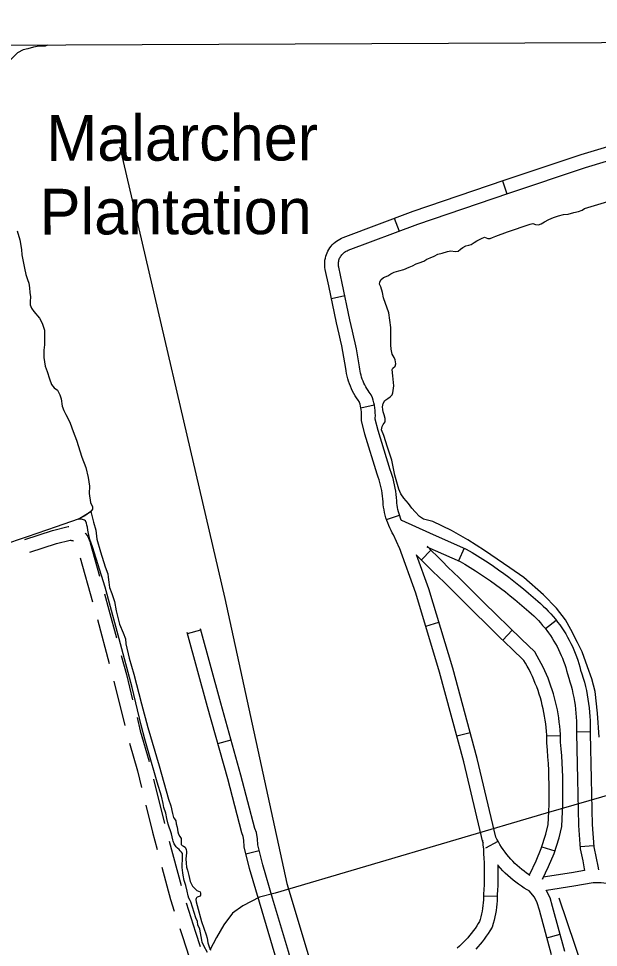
# Model space of a CAD drawing. Extents: x 3419139 to 3457078, y 540382 to 565875.
# Drawn here: x 3441511 to 3442779, y 562061 to 564093 of the extents above; entities that cross this region are included whole.
import ezdxf

# ---------------------------------------------------------------- set-up
doc = ezdxf.new("R2010")
doc.units = 0
for name, color, linetype in [('V-BLDG-IDEN', 7, 'Continuous'), ('V-GRID-FRAM', 7, 'Continuous'), ('V-ROAD-CNTR', 7, 'Continuous'), ('V-TOPO-SHOR', 7, 'Continuous')]:
    doc.layers.add(name, color=color, linetype=linetype)

msp = doc.modelspace()

# ---------------------------------------------------------------- linework, layer by layer
at = {"layer": 'V-GRID-FRAM'}
msp.add_lwpolyline([(3423200.9, 563955.1), (3454837.9, 564093.1), (3454925.2, 545910.2), (3423272.3, 545772.1), (3423200.9, 563955.1)], dxfattribs=at)
at = {"layer": 'V-ROAD-CNTR'}
for p, q in [((3442569.4, 563738.2), (3442579.1, 563709.8)), ((3442332.8, 563656.1), (3442343.4, 563628)), ((3442195.2, 563480.8), (3442224.5, 563487)), ((3442259.8, 563241.3), (3442289.1, 563247.7)), ((3442315.6, 562997.4), (3442344.2, 563006.5)), ((3442392.1, 562908.7), (3442413.1, 562930.1)), ((3442485.7, 562934.2), (3442473.6, 562906.8)), ((3441645.8, 562913.2), (3441672.8, 562816.9)), ((3441683.5, 562778.4), (3441709.4, 562681.8)), ((3442401.5, 562763.5), (3442430.2, 562772.2)), ((3442687.2, 562776.3), (3442663.5, 562757.8)), ((3441880.6, 562747.6), (3441909.5, 562755.6)), ((3442570, 562733.1), (3442590.9, 562754.6)), ((3441719.6, 562643.1), (3441743.7, 562546.1)), ((3442469.5, 562523.4), (3442498.5, 562531.2)), ((3442666.2, 562523.4), (3442696.2, 562524.5)), ((3442761.4, 562531.6), (3442731.4, 562532.2)), ((3441947.1, 562506.6), (3441976, 562514.6)), ((3441806.5, 562428.7), (3441830.6, 562331.6)), ((3441840.7, 562292.9), (3441866.5, 562196.3)), ((3442533.4, 562278.4), (3442559.7, 562292.9)), ((3442008.4, 562265.7), (3442037.6, 562272.9)), ((3442655.6, 562280.9), (3442684.1, 562271.7)), ((3442769.2, 562283.1), (3442739.3, 562281)), ((3442558.2, 562172.2), (3442528.2, 562172.5)), ((3442666.5, 562081.6), (3442695.5, 562089.5))]:
    msp.add_line(p, q, dxfattribs=at)
for points in [[(3442344.4, 562934), (3442331, 562963.7), (3442328.5, 562967.9), (3442325.7, 562973.1), (3442323, 562978.5), (3442320.6, 562983.9), (3442318.4, 562989.5), (3442316.4, 562995.1), (3442314.6, 563000.8), (3442313, 563006.6), (3442311.6, 563012.4), (3442310.4, 563018.3), (3442309.5, 563024.2), (3442308.8, 563030.1), (3442308.3, 563035.9), (3442307.9, 563042.3), (3442307.3, 563048.3), (3442306.5, 563054.4), (3442305.5, 563060.4), (3442304.3, 563066.4), (3442302.9, 563072.4), (3442301.3, 563078.3), (3442299.6, 563084.1), (3442297.7, 563089.9), (3442295.3, 563096.3), (3442268.8, 563183.9), (3442260.9, 563213.3), (3442261.4, 563220.3), (3442261.5, 563224.5), (3442261.4, 563228.7), (3442261.1, 563232.9), (3442260.6, 563237.1), (3442259.9, 563241.2), (3442259, 563245.3), (3442257.9, 563249.3), (3442256.6, 563253.3), (3442255.8, 563255.5), (3442253.8, 563258.1), (3442250.5, 563262.9), (3442247.3, 563267.8), (3442244.4, 563272.8), (3442241.7, 563277.9), (3442239.1, 563283.1), (3442236.8, 563288.5), (3442234.7, 563293.9), (3442232.9, 563299.4), (3442231.2, 563304.9), (3442229.8, 563310.6), (3442228.6, 563316.2), (3442227.7, 563322), (3442227, 563327.1), (3442225, 563339.5), (3442222.8, 563352.1), (3442220.5, 563364.7), (3442218, 563377.3), (3442215.4, 563389.8), (3442212.6, 563402.3), (3442209.6, 563414.7), (3442206.5, 563427.5), (3442189.4, 563508.2), (3442181.8, 563544.1), (3442181.1, 563548.1), (3442180.8, 563552.2), (3442180.7, 563556.4), (3442180.9, 563560.6), (3442181.3, 563564.7), (3442182.1, 563568.8), (3442183.1, 563572.9), (3442184.4, 563576.8), (3442185.9, 563580.7), (3442187.7, 563584.5), (3442189.8, 563588.1), (3442192.1, 563591.6), (3442194.6, 563594.9), (3442197.3, 563598.1), (3442200.2, 563601), (3442203.4, 563603.8), (3442206.7, 563606.3), (3442210.1, 563608.6), (3442213.8, 563610.7), (3442217.5, 563612.6), (3442221.1, 563614), (3442374, 563671.6), (3442573.5, 563739.6), (3442741.8, 563795.7), (3442925.7, 563851.2)], [(3442348.6, 562994.8), (3442348.2, 562995.7), (3442346.4, 563000.2), (3442344.8, 563004.7), (3442343.3, 563009.3), (3442342, 563014), (3442340.9, 563018.7), (3442340, 563023.5), (3442339.2, 563028.3), (3442338.7, 563033.1), (3442338.3, 563038.1), (3442337.8, 563044.9), (3442337.1, 563051.9), (3442336.1, 563058.8), (3442335, 563065.8), (3442333.6, 563072.7), (3442332, 563079.6), (3442330.2, 563086.4), (3442328.2, 563093.1), (3442326, 563099.8), (3442323.8, 563105.8), (3442297.6, 563192.1), (3442291.2, 563216.3), (3442291.4, 563219.1), (3442291.5, 563224.6), (3442291.3, 563230.2), (3442290.9, 563235.8), (3442290.2, 563241.4), (3442289.3, 563246.9), (3442288.1, 563252.4), (3442286.7, 563257.8), (3442285, 563263.1), (3442282.4, 563270.1), (3442278, 563275.8), (3442275.4, 563279.6), (3442272.9, 563283.5), (3442270.6, 563287.4), (3442268.4, 563291.5), (3442266.4, 563295.6), (3442264.6, 563299.8), (3442262.9, 563304.1), (3442261.5, 563308.5), (3442260.2, 563312.9), (3442259.1, 563317.3), (3442258.1, 563321.8), (3442257.4, 563326.3), (3442256.7, 563331.4), (3442254.6, 563344.5), (3442252.4, 563357.5), (3442249.9, 563370.4), (3442247.4, 563383.3), (3442244.7, 563396.1), (3442241.8, 563409), (3442238.8, 563421.8), (3442235.7, 563434.2), (3442218.7, 563514.5), (3442211.3, 563549.5), (3442210.9, 563551.7), (3442210.7, 563553.9), (3442210.7, 563556.1), (3442210.8, 563558.2), (3442211, 563560.4), (3442211.4, 563562.5), (3442211.9, 563564.6), (3442212.6, 563566.6), (3442213.4, 563568.6), (3442214.3, 563570.6), (3442215.4, 563572.5), (3442216.6, 563574.3), (3442217.9, 563576), (3442219.3, 563577.7), (3442220.8, 563579.2), (3442222.5, 563580.6), (3442224.2, 563581.9), (3442226, 563583.1), (3442227.8, 563584.2), (3442229.8, 563585.2), (3442232.1, 563586.1), (3442384.2, 563643.4), (3442583.1, 563711.2), (3442750.9, 563767.1), (3442934.5, 563822.5)], [(3442348.8, 562995.8), (3442410, 562967.7), (3442490.4, 562932.1), (3442503, 562924.7), (3442514.8, 562917.5), (3442526.5, 562910.1), (3442538, 562902.6), (3442549.5, 562894.9), (3442560.9, 562887), (3442572.1, 562878.9), (3442583.2, 562870.7), (3442594.2, 562862.3), (3442605.1, 562853.7), (3442615.8, 562845), (3442626.4, 562836.1), (3442636.9, 562827), (3442647.1, 562818), (3442652.8, 562813), (3442658.6, 562807.7), (3442664.2, 562802.2), (3442669.7, 562796.5), (3442675, 562790.8), (3442680.2, 562784.8), (3442685.2, 562778.8), (3442690, 562772.6), (3442694.7, 562766.3), (3442699.2, 562759.8), (3442703.5, 562753.2), (3442707.7, 562746.6), (3442711.6, 562739.8), (3442715.4, 562732.9), (3442719, 562725.9), (3442722.4, 562718.8), (3442725.6, 562711.6), (3442728.6, 562704.3), (3442731.4, 562697), (3442734, 562689.6), (3442736.4, 562682.1), (3442738.6, 562674.6), (3442740.4, 562667.6), (3442743.2, 562659.2), (3442745.9, 562650.2), (3442748.5, 562641), (3442750.8, 562631.8), (3442752.9, 562622.6), (3442754.7, 562613.3), (3442756.4, 562604), (3442757.8, 562594.6), (3442759, 562585.2), (3442759.9, 562575.8), (3442760.7, 562566.3), (3442761.2, 562556.9), (3442761.5, 562547.4), (3442761.5, 562537.9), (3442761.3, 562528.9), (3442763.2, 562429.6), (3442765.9, 562329.2)], [(3441524.9, 562953.6), (3441585.7, 562973.1), (3441619.8, 562981.5), (3441620.8, 562981.6)], [(3441656.7, 562967.4), (3441658.2, 562965.8), (3441660.5, 562962.8), (3441662.6, 562959.5), (3441664.4, 562956.1), (3441665.9, 562952.6), (3441667, 562948.9), (3441667.7, 562946.2), (3441688.2, 562873.2)], [(3441535.7, 562925.5), (3441593.9, 562944.2), (3441624, 562951.7), (3441624.3, 562951.7), (3441625.5, 562951.6), (3441626.7, 562951.4), (3441627.9, 562951.1), (3441629.1, 562950.8), (3441630.3, 562950.3), (3441631.4, 562949.7), (3441631.5, 562949.7)], [(3442527.6, 562289.4), (3442526.7, 562291.3), (3442484.7, 562467), (3442431.8, 562663.1), (3442379.7, 562835.6), (3442343.9, 562935.1)], [(3442404, 562937.5), (3442476.7, 562905.4), (3442487.5, 562899), (3442498.9, 562892), (3442510.3, 562884.9), (3442521.5, 562877.6), (3442532.6, 562870.1), (3442543.6, 562862.5), (3442554.4, 562854.7), (3442565.2, 562846.7), (3442575.8, 562838.6), (3442586.4, 562830.3), (3442596.7, 562821.8), (3442607, 562813.2), (3442617.1, 562804.5), (3442627.3, 562795.5), (3442632.8, 562790.7), (3442638, 562785.9), (3442643, 562781), (3442647.9, 562775.9), (3442652.7, 562770.7), (3442657.3, 562765.4), (3442661.8, 562760), (3442666.2, 562754.4), (3442670.3, 562748.8), (3442674.4, 562743), (3442678.2, 562737.1), (3442682, 562731.1), (3442685.5, 562725), (3442688.9, 562718.8), (3442692.1, 562712.6), (3442695.1, 562706.2), (3442698, 562699.8), (3442700.7, 562693.3), (3442703.2, 562686.7), (3442705.5, 562680), (3442707.7, 562673.3), (3442709.7, 562666.6), (3442711.6, 562659.1), (3442714.6, 562650.2), (3442717.1, 562641.8), (3442719.4, 562633.4), (3442721.6, 562624.9), (3442723.5, 562616.3), (3442725.2, 562607.7), (3442726.8, 562599.1), (3442728.1, 562590.5), (3442729.2, 562581.8), (3442730.1, 562573.1), (3442730.7, 562564.4), (3442731.2, 562555.6), (3442731.5, 562546.9), (3442731.5, 562538.1), (3442731.3, 562528.9), (3442733.2, 562428.9), (3442735.9, 562328.3)], [(3442749.1, 562229.3), (3442720.7, 562224.2), (3442658.8, 562214.6), (3442657.3, 562210), (3442670.2, 562237.8), (3442682.4, 562266.5), (3442693.3, 562300.2), (3442699.4, 562325.6), (3442700.3, 562342.1), (3442700.9, 562357.4), (3442701.4, 562372.7), (3442701.6, 562388), (3442701.7, 562403.3), (3442701.5, 562418.6), (3442701.2, 562433.8), (3442700.6, 562449.1), (3442699.9, 562464.4), (3442699, 562479.6), (3442697.8, 562494.9), (3442696.6, 562509.5), (3442696.5, 562517.8), (3442696.1, 562526.8), (3442695.6, 562535.8), (3442694.8, 562544.8), (3442693.8, 562553.7), (3442692.6, 562562.7), (3442691.2, 562571.6), (3442689.6, 562580.4), (3442687.8, 562589.3), (3442685.7, 562598.1), (3442683.5, 562606.8), (3442681, 562615.5), (3442678.4, 562624.1), (3442675.5, 562632.6), (3442672.4, 562641.1), (3442669.2, 562649.5), (3442665.7, 562657.8), (3442662, 562666.1), (3442658.2, 562674.2), (3442654.1, 562682.3), (3442649.9, 562690.2), (3442645.4, 562698.1), (3442639.9, 562707.4), (3442610.9, 562735.3), (3442583.4, 562761.9), (3442556.1, 562788.6), (3442528.9, 562815.4), (3442501.8, 562842.3), (3442474.7, 562869.5), (3442462.4, 562881.3), (3442450.3, 562893), (3442438.3, 562904.8), (3442426.4, 562916.7), (3442414.4, 562928.8), (3442404.5, 562938.5)], [(3442629.3, 562218.4), (3442627.5, 562219.5), (3442622, 562223.3), (3442616.7, 562227.2), (3442611.5, 562231.3), (3442606.5, 562235.6), (3442601.5, 562240), (3442596.7, 562244.6), (3442592.1, 562249.3), (3442587.6, 562254.1), (3442583.2, 562259.1), (3442579, 562264.2), (3442575, 562269.4), (3442571.1, 562274.8), (3442567.4, 562280.2), (3442563.9, 562285.8), (3442560.5, 562291.5), (3442557.3, 562297.3), (3442555, 562301.8), (3442513.8, 562474.4), (3442460.7, 562671.4), (3442408.2, 562845), (3442381.3, 562919.9)], [(3442628.3, 562217.8), (3442629.3, 562220.9), (3442642.8, 562250), (3442654.3, 562277), (3442664.4, 562308.4), (3442669.6, 562330), (3442670.3, 562343.6), (3442670.9, 562358.5), (3442671.4, 562373.4), (3442671.6, 562388.3), (3442671.7, 562403.2), (3442671.5, 562418.1), (3442671.2, 562433), (3442670.7, 562447.9), (3442669.9, 562462.8), (3442669, 562477.6), (3442667.9, 562492.5), (3442666.6, 562508), (3442666.5, 562517), (3442666.2, 562525.3), (3442665.7, 562533.6), (3442664.9, 562541.9), (3442664, 562550.1), (3442662.9, 562558.3), (3442661.6, 562566.5), (3442660.2, 562574.7), (3442658.5, 562582.8), (3442656.6, 562590.9), (3442654.5, 562599), (3442652.3, 562607), (3442649.8, 562614.9), (3442647.2, 562622.8), (3442644.4, 562630.6), (3442641.3, 562638.3), (3442638.2, 562646), (3442634.8, 562653.6), (3442631.2, 562661.1), (3442627.5, 562668.5), (3442623.6, 562675.8), (3442619.5, 562683), (3442616.2, 562688.6), (3442590, 562713.7), (3442562.5, 562740.4), (3442535.1, 562767.2), (3442507.8, 562794.1), (3442480.6, 562821.1), (3442453.7, 562848.1), (3442441.6, 562859.7), (3442429.4, 562871.5), (3442417.2, 562883.5), (3442405.1, 562895.5), (3442393.2, 562907.5), (3442382.2, 562918.4)], [(3444537.3, 562898.5), (3443302.9, 562539.3), (3442665.3, 562354.1), (3442072.4, 562179.7), (3442037.8, 562170.6), (3442001.4, 562152), (3441979.2, 562135.6), (3441959.9, 562109.8), (3441943.8, 562082.4), (3441929.2, 562054.6)], [(3441699, 562834.7), (3441708.9, 562799.5), (3441725.3, 562738.2)], [(3442114.8, 561904.7), (3442096.6, 561955.9), (3442072.5, 562043.8), (3442037.8, 562159.9), (3442016.4, 562233.5), (3442004.7, 562281), (3442004.1, 562295.2), (3442002.6, 562303.5), (3441999.4, 562311.2), (3441968.6, 562429.6), (3441924.7, 562586.8), (3441880, 562749.6)], [(3442133.2, 561942.6), (3442125.2, 561964.9), (3442101.3, 562052.1), (3442066.6, 562168.4), (3442045.4, 562241.3), (3442034.5, 562285.3), (3442033.9, 562298.5), (3442031.5, 562312), (3442027.9, 562320.7), (3441997.6, 562437.5), (3441953.6, 562594.8), (3441909, 562757.5)], [(3441735.7, 562699.6), (3441746.9, 562657.7), (3441760.5, 562602.7)], [(3441770.2, 562563.9), (3441777.4, 562534.8), (3441796.5, 562467.4)], [(3444390.3, 562524.7), (3444235.9, 562480), (3444021.9, 562422.6), (3443833.8, 562375.3), (3443657.2, 562327.5), (3443499.7, 562291.7), (3443350.6, 562263.1), (3443162.8, 562238), (3442969.4, 562215.5), (3442829.2, 562197.3), (3442803.7, 562199.9), (3442797.2, 562200.8), (3442791.1, 562201.4), (3442785, 562201.8), (3442778.8, 562202.1), (3442772.7, 562202.2), (3442767.6, 562202.2), (3442725.7, 562194.6), (3442665.5, 562185.3)], [(3441754, 562507.4), (3441771.1, 562447.1), (3441780, 562410.9)], [(3441789.7, 562372.1), (3441804.2, 562313.2), (3441814.4, 562275.2)], [(3442736, 562327.7), (3442739.6, 562276.7), (3442744.9, 562250.4), (3442748.3, 562232.8), (3442749, 562229)], [(3442765.9, 562329.8), (3442769.4, 562280.7), (3442774.3, 562256.2), (3442777.9, 562238.2), (3442779.1, 562230.8)], [(3442525.9, 562295.2), (3442526.8, 562285.3), (3442527.6, 562275.5), (3442528.2, 562265.7), (3442528.7, 562255.9), (3442529.1, 562246.1), (3442529.4, 562236.3), (3442529.5, 562226.6), (3442529.5, 562216.8), (3442529.4, 562207), (3442529.1, 562197.3), (3442528.8, 562187.6), (3442528.2, 562177.5), (3442528.2, 562170.8), (3442527.9, 562164.6), (3442527.4, 562158.4), (3442526.8, 562152.3), (3442525.9, 562146.1), (3442524.9, 562140), (3442523.6, 562133.9), (3442522.2, 562127.8), (3442520.5, 562121.7), (3442519.2, 562117.3), (3442516.6, 562113.1), (3442513.1, 562107.6), (3442509.5, 562102.2), (3442505.6, 562097), (3442501.7, 562091.8), (3442497.6, 562086.8), (3442493.4, 562081.9), (3442489, 562077.1), (3442484.5, 562072.4), (3442479.9, 562067.9), (3442475.2, 562063.5), (3442470.4, 562059.3)], [(3441824.7, 562236.5), (3441843.6, 562165.7), (3441851.8, 562140.3)], [(3442559.3, 562241), (3442559.4, 562236.9), (3442559.5, 562226.8), (3442559.5, 562216.6), (3442559.4, 562206.5), (3442559.1, 562196.3), (3442558.7, 562186.2), (3442558.2, 562176.6), (3442558.2, 562170), (3442557.9, 562162.9), (3442557.3, 562155.7), (3442556.6, 562148.6), (3442555.6, 562141.5), (3442554.4, 562134.4), (3442552.9, 562127.4), (3442551.2, 562120.4), (3442549.3, 562113.4), (3442546.7, 562105), (3442542.1, 562097.3), (3442538.1, 562091.1), (3442534, 562085), (3442529.7, 562079), (3442525.2, 562073.2), (3442520.6, 562067.5), (3442515.8, 562062), (3442510.9, 562056.6)], [(3442676.7, 562044.4), (3442650.2, 562141.9), (3442645.6, 562158), (3442639.2, 562170.9), (3442627.6, 562184.3), (3442623.5, 562186.6), (3442617, 562190.5), (3442610.7, 562194.6), (3442604.5, 562198.9), (3442598.5, 562203.4), (3442592.6, 562208.1), (3442586.8, 562212.9), (3442581.2, 562217.9), (3442575.7, 562223.1), (3442570.4, 562228.5), (3442565.3, 562234), (3442560.4, 562239.7), (3442559.1, 562241.1)], [(3442705.6, 562052.1), (3442679.1, 562150), (3442673.7, 562168.9), (3442665.2, 562185.8)], [(3441877.7, 562157.9), (3441898.4, 562093.8), (3441908.2, 562062.7)], [(3441864.1, 562102.2), (3441869.8, 562084.7), (3441891.3, 562016.7), (3441894.7, 562007.1)]]:
    msp.add_lwpolyline(points, dxfattribs=at)
at = {"layer": 'V-TOPO-SHOR'}
msp.add_line((3441641.3, 562997.5), (3441669.2, 563014.8), dxfattribs=at)
for points in [[(3441574.6, 564035.2), (3441569.5, 564032.9), (3441556.5, 564032.4), (3441543.5, 564030.4), (3441531.8, 564027.1), (3441521.5, 564024.4), (3441509.2, 564018.3), (3441503.7, 564012.9), (3441489.2, 563998.6), (3441479.6, 563987.8), (3441473.2, 563977.5)], [(3441732.4, 563811.6), (3441962.1, 562824.3), (3442097.7, 562200.8), (3442162.2, 561987.2)], [(3442309.3, 563482.3), (3442307.2, 563493.4), (3442303.7, 563506.2), (3442300.6, 563512.1), (3442300.9, 563516.7), (3442303.1, 563521.8), (3442309.1, 563526.7), (3442318.4, 563530.2), (3442325.4, 563534.3), (3442332.8, 563538.4), (3442342.5, 563541.3), (3442353.4, 563543.8), (3442365.5, 563549.2), (3442372.8, 563552), (3442380.8, 563556.6), (3442387.3, 563559), (3442397.3, 563562), (3442404.3, 563566.4), (3442411, 563569.9), (3442419.8, 563573.1), (3442428.3, 563577.5), (3442437.8, 563580.1), (3442449.3, 563583.7), (3442456.6, 563585), (3442466.2, 563583.3), (3442472.4, 563584.1), (3442478, 563588.2), (3442482.5, 563592.2), (3442489.1, 563595.5), (3442495.8, 563597.4), (3442501.2, 563598.7), (3442507.3, 563602.8), (3442513.5, 563606.7), (3442523.5, 563612.2), (3442530.4, 563614.5), (3442537.1, 563612.1), (3442542.3, 563611.7), (3442547.9, 563614), (3442555, 563616.8), (3442580.2, 563626.5), (3442630.2, 563643.6), (3442635.9, 563644.4), (3442641.5, 563642.8), (3442648, 563642), (3442653.9, 563644.1), (3442661.5, 563648.6), (3442670.9, 563653.3), (3442681.2, 563658.1), (3442692.1, 563661.8), (3442702.7, 563664.6), (3442713.4, 563665.5), (3442725.8, 563668.5), (3442735.8, 563670.9), (3442743.7, 563673.9), (3442748.8, 563677.2), (3442848.7, 563707.1)], [(3441508, 563628.6), (3441513.9, 563609), (3441517.9, 563587.9), (3441518.3, 563576), (3441524.4, 563547.3), (3441527.2, 563532.8), (3441530.5, 563522.2), (3441533.5, 563513.9), (3441534.8, 563503.9), (3441535.6, 563493.7), (3441537.3, 563484.5), (3441536.6, 563474.3), (3441536.7, 563466.7), (3441539.8, 563459.5), (3441544.8, 563452.4), (3441557.1, 563437.3), (3441562.6, 563426.4), (3441567.6, 563411.4), (3441568.2, 563390.1), (3441567.7, 563379.5), (3441566.6, 563367.9), (3441566.1, 563351.3), (3441569.3, 563332.7), (3441573.7, 563321.1), (3441578.5, 563304.5), (3441583, 563292.6), (3441588.8, 563284.9), (3441596.1, 563279.8), (3441601.5, 563269.8), (3441604.3, 563260.9), (3441606.6, 563244.8), (3441610.1, 563235.8), (3441614.9, 563227.1), (3441619.9, 563217.1), (3441623.9, 563207.6), (3441630.8, 563189.7), (3441637.8, 563170.9), (3441649.2, 563133.4), (3441658.6, 563110.6), (3441663.3, 563088.6), (3441666, 563069.9), (3441665.8, 563053.9), (3441668.8, 563034.5), (3441672.6, 563025), (3441672.7, 563019.7), (3441669.2, 563014.8), (3441655.8, 563005.4), (3441641.3, 562997.5), (3441593.1, 562981.3), (3441530.1, 562959), (3441473.5, 562940.4)], [(3442780.9, 562521.1), (3442777.1, 562573.2), (3442772, 562620.8), (3442765, 562648.2), (3442755.2, 562674.4), (3442743.6, 562707.4), (3442733.3, 562728.2), (3442718.8, 562756.4), (3442707.2, 562777.2), (3442687.4, 562803.3), (3442659.1, 562832.5), (3442616.4, 562870.1), (3442585.9, 562891.1), (3442530.1, 562929.4), (3442493.8, 562952.7), (3442457.8, 562972.8), (3442417.2, 562992.4), (3442397.1, 562998.1), (3442387.9, 563003.9), (3442378.6, 563013.5), (3442371.4, 563022.2), (3442363.6, 563032.1), (3442353.7, 563043.6), (3442347.3, 563053.5), (3442342.8, 563063.2), (3442334, 563094.1), (3442327.3, 563126.8), (3442318.2, 563155.1), (3442310.2, 563180.5), (3442304.6, 563193.4), (3442306.1, 563200.8), (3442308.6, 563204.6), (3442312.9, 563210.4), (3442313.1, 563217.7), (3442310.7, 563226.2), (3442308.8, 563232.5), (3442307.5, 563237.8), (3442307.2, 563243.4), (3442308.3, 563251), (3442312.1, 563257.3), (3442319.1, 563262.1), (3442323.7, 563265.4), (3442328.2, 563270), (3442329.8, 563274.2), (3442332.1, 563289.8), (3442330, 563311.4), (3442328.2, 563325.2), (3442330, 563328.3), (3442334.5, 563332.2), (3442336.6, 563337.8), (3442334.8, 563346.3), (3442332.6, 563351.3), (3442328.4, 563358.9), (3442325.9, 563369.6), (3442325.2, 563379.3), (3442325.3, 563388.5), (3442325.4, 563406.3), (3442325.5, 563417.5), (3442320.8, 563449.4), (3442309.3, 563482.3)], [(3441669.2, 563014.8), (3441675.2, 562991.5), (3441679.9, 562973.7), (3441682.5, 562953.9), (3441690.5, 562926.5), (3441700.5, 562893.6), (3441706.6, 562877.8), (3441707.2, 562871), (3441708.5, 562860), (3441710.2, 562848.4), (3441714.9, 562835.4), (3441721.2, 562817.8), (3441724.3, 562797.5), (3441732, 562768), (3441739.9, 562749.3), (3441744.8, 562735.6), (3441746.1, 562724.9), (3441753.4, 562693.6), (3441763, 562658.4), (3441779.8, 562593.4), (3441793.8, 562541.8), (3441818.6, 562457.7), (3441839, 562385.3), (3441844.2, 562370.5), (3441847.7, 562353.6), (3441849.9, 562344.9), (3441852.2, 562341.7), (3441855.1, 562337.4), (3441856.2, 562331.2), (3441857.8, 562323.7), (3441859.7, 562313.9), (3441861.3, 562308.6), (3441863.8, 562303.6), (3441866.5, 562298.8), (3441866.7, 562294.9), (3441866.6, 562290.8), (3441867.1, 562285.8), (3441868.6, 562283.7), (3441871.8, 562282.3), (3441875.7, 562279.8), (3441877.7, 562275.2), (3441878.1, 562270.9), (3441878.6, 562267.5), (3441876.9, 562254.5), (3441877.5, 562244.9), (3441878.6, 562236.3), (3441880.4, 562229.9), (3441883.5, 562218.2), (3441886.1, 562204.8), (3441891.5, 562194.5), (3441894.9, 562191), (3441897.9, 562188.3), (3441901, 562185.5), (3441904.9, 562184.1), (3441908.5, 562182.3), (3441909.4, 562179.3), (3441909.4, 562175.2), (3441906.6, 562172.3), (3441904.1, 562171.1), (3441901.6, 562170.5), (3441900.2, 562169.3), (3441899.5, 562167.8), (3441899.1, 562165.5), (3441899.3, 562160.7), (3441901.5, 562152.5), (3441911, 562117.1), (3441921.3, 562088.1), (3441923.6, 562081.2), (3441924.8, 562070.5), (3441928, 562062.3), (3441931.1, 562055)], [(3441916.6, 562064.2), (3441913, 562072.2), (3441912.1, 562076.3), (3441910.4, 562084.5), (3441907.3, 562100.5), (3441903.5, 562110.1), (3441902.4, 562117.1), (3441899.2, 562125.6), (3441888.1, 562160.3), (3441886.3, 562163.3), (3441883.6, 562168.3), (3441882, 562173.8), (3441879.8, 562183.6), (3441876.7, 562196.2), (3441873.4, 562207.1), (3441870.9, 562219), (3441870.1, 562224.2), (3441868.8, 562235.4), (3441869.8, 562258.9), (3441869.4, 562266.2), (3441867.2, 562269.2), (3441864.9, 562272.1), (3441862.2, 562274.9), (3441858.8, 562277.9), (3441855.9, 562280.6), (3441854.1, 562282.7), (3441851.8, 562287), (3441849.3, 562293), (3441848.9, 562296.4), (3441845.8, 562309.2), (3441838.4, 562330.2), (3441835.3, 562343), (3441832.9, 562354.2), (3441829.1, 562366.7), (3441827.1, 562375.6), (3441823.8, 562391.4), (3441814, 562422.4), (3441794.4, 562490.9), (3441787.1, 562516.5), (3441779.5, 562547.3), (3441759.3, 562629.7), (3441730.9, 562735.9), (3441700.5, 562849.1), (3441673, 562937.3), (3441666.8, 562953.1), (3441664.1, 562966.3), (3441663, 562973.4), (3441661.7, 562980.4), (3441660.8, 562984.5), (3441659.5, 562989.3), (3441657.2, 562994.1), (3441655.2, 562995.7), (3441652.9, 562996), (3441648.6, 562997.6), (3441646.5, 562997.6), (3441641.3, 562997.5)], [(3444286.7, 561170.1), (3444020.6, 561238.3), (3443708.2, 561312.1), (3443447.9, 561362.9), (3443268.6, 561385.3), (3443170.4, 561384.8), (3443043.3, 561378.5), (3442968.2, 561378.2), (3442927.7, 561389.6), (3442904.4, 561412.6), (3442898.5, 561453), (3442787, 561839.7), (3442745.8, 562012.9), (3442693.1, 562168.7)], [(3441924, 562049.3), (3441916.6, 562064.2)]]:
    msp.add_lwpolyline(points, dxfattribs=at)

# ---------------------------------------------------------------- texts
at = {"layer": 'V-BLDG-IDEN'}
for s, p in [('Malarcher', (3441571.9, 563781.8)), ('Plantation', (3441557.6, 563620.6))]:
    msp.add_text(s, height=100, rotation=0.088, dxfattribs=at).set_placement(p)

doc.saveas('drawing.dxf')
